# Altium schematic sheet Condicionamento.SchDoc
size A
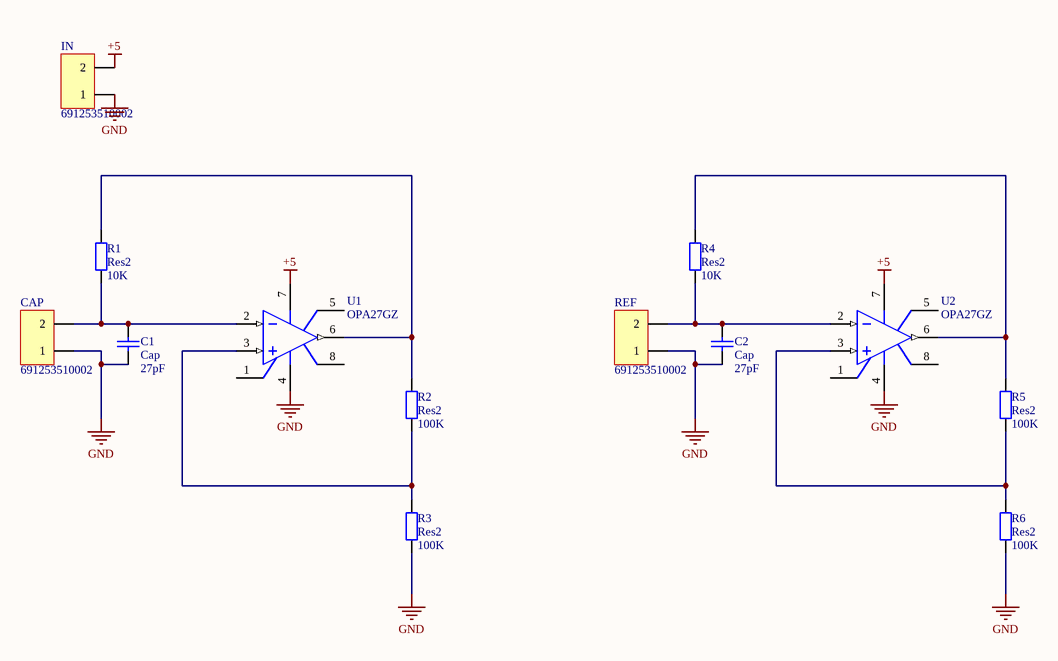
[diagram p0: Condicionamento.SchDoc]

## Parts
C1  Cap  value 27pF  [RAD-0.3]
C2  Cap  value 27pF  [RAD-0.3]
CAP  691253510002  [691253510002]
IN  691253510002  [691253510002]
R1  Res2  value 10K  [AXIAL-0.4]
R2  Res2  value 100K  [AXIAL-0.4]
R3  Res2  value 100K  [AXIAL-0.4]
R4  Res2  value 10K  [AXIAL-0.4]
R5  Res2  value 100K  [AXIAL-0.4]
R6  Res2  value 100K  [AXIAL-0.4]
REF  691253510002  [691253510002]
U1  OPA27GZ  [ZZ161]
U2  OPA27GZ  [ZZ161]

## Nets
+5: IN.2 U1.7(V+) U2.7(V+)
GND: C1.1 C2.1 CAP.1 IN.1 R3.1 R6.1 REF.1 U1.4(V-) U2.4(V-)
NetC1_2: C1.2 CAP.2 R1.1 U1.2(IN-)
NetC2_2: C2.2 R4.1 REF.2 U2.2(IN-)
NetR1_2: R1.2 R2.2 U1.6(OUT)
NetR2_1: R2.1 R3.2 U1.3(IN+)
NetR4_2: R4.2 R5.2 U2.6(OUT)
NetR5_1: R5.1 R6.2 U2.3(IN+)

Not connected (* = marked no-connect by the designer): U1 1(OS_TRIM) 5(NC) 8(OS_TRIM); U2 1(OS_TRIM) 5(NC) 8(OS_TRIM)

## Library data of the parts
C1 C2 = Cap: Capacitor
CAP IN REF = 691253510002: Horizontal Cable Entry with Rising Cage Clamp, Serie 2535 - 5.08mm; Manufacturer: Wurth Elektronik; ComponentLink1 Description: Manufacturer; ComponentLink2 Description: Datasheet; NoPins: 2
R1-R6 = Res2: Resistor
U1 U2 = OPA27GZ: Ultra-Low-Noise Precision Operational Amplifiers; Note: Pin 5 is No internal Connection (NC) pin.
